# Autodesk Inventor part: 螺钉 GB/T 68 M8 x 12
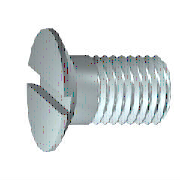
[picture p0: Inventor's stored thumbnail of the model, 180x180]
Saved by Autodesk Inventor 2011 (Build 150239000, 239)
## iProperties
Created: 2010-02
Part Number: 螺钉 GB/T 68 M8 x 12
Material: 低炭钢
Description: 开槽沉头螺钉
Document SubType Name: Modeling
Standard: GB/T 68-2000
Designer: user
Standard Revision: 2000
Standards Organization: GB
Language: zh-CN
Size Designation: M8x12
Categories: <MemberInstance><Categories><Category DisplayName="紧固件" InternalName="e4da775c-781d-43d5-af7c-5136215cf5a6" Mnemonic="FSTN"><Category DisplayName="螺栓" InternalN
Density: 1 g/cm^3
IsCustomPart: 1
Author: user
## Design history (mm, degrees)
body "Solid1"
sketch "Sketch1"
  geometry: L1 (5.056, 3.594)-(0.75, 7.9); L2 (0.75, 7.9)-(0, 7.9); L3 (0, 7.9)-(0, 0); L4 (0, 0)-(12, 0); L5 (12, 4)-(7.15, 4); L6 (7.15, 4)-(6.383, 3.594); L7 (6.383, 3.594)-(5.056, 3.594); L8 (7.15, 4)-(4.65, 4); L9 (12, 0)-(12, 4); L10 (-2.4, 0)-(14.4, 0) reference; L11 (0, 9.48)-(0, -1.58) reference
  constraints: 18 end point, 4 parallel, 2 collinear, 2 perpendicular, 1 horizontal, 1 point on line
  dimensions: "d0" = 12 distance of L3.end L4.end (= NLG); "d1" = 45 deg angle of L1 L4 (= 0.5 x SEWI); "d2" = 0.76681 horizontal distance of L5.end L6.end (= GAL); "d3" = 4.85 distance from line of L9 L5.end (= GEL); "d4" = 4.65 distance from line of L8.end L3 (= KOH); "d5" = 7.188 diameter of L6.end L4 (= BDM); "d6" = 8 diameter of L5 L4 (= GD); "d7" = 15.8 diameter of L2 L4 (= KOD)
workplane "Work Plane1"
fillet "Fillet" dims "d41" = 2 (= RR)
revolve "Body" stored, may be unused: angle "d19" = 90 deg
sketch "Sketch2"
  geometry: L1 (7.9, -1)-(-7.9, -1); L2 (-7.9, -1)-(-7.9, 1); L3 (-7.9, 1)-(7.9, 1); L4 (7.9, 1)-(7.9, -1); L5 (0, 1)-(0, -1); L6 (-7.9, 0)-(7.9, 0); L7 (0, 7.9)-(0, 0) reference; 2 further points
  constraints: 12 end point, 5 midpoint, 2 parallel, 1 collinear, 1 horizontal, 1 perpendicular
  dimensions: "d15" = 2 distance of L3.end L1.start (= SBR); "d16" = 15.8 distance of L1.start L1.end (= KOD)
extrude "Slot" cut sketch "Sketch2" distance "d8" = 2.3 (= STI); taper "d9" = 0 deg
feature "Thread" dims "d10" = 4.85 (= GEL), "d11" = 0
chamfer "Chamfer1" distance "d12" = 0.76681 (= -0.5 x SPD + 0.5 x GD); stored, may be unused: second distance "d13" = 0.38341 (= 0.5 x GAL), angle "d35" = 45 deg
other parameters: "NLG" = 12 [user parameter; used in 1 equation term], "GAL" = 0.76681 (= 0.61345 x PTC) [user parameter; used in 2 equation terms], "GEL" = 4.85 [user parameter; used in 2 equation terms], "KOH" = 4.65 [user parameter; used in 1 equation term], "KOD" = 15.8 [user parameter; used in 2 equation terms], "SEWI" = 90 deg [user parameter; used in 1 equation term], "BDM" = 7.188 [user parameter; used in 1 equation term], "GD" = 8 (= NND) [user parameter; used in 2 equation terms], "SBR" = 2 [user parameter; used in 1 equation term], "STI" = 2.3 [user parameter; used in 1 equation term], "d17" = 0, "SPD" = 6.46637 (= NND - 1.2269 x PTC) [user parameter; used in 1 equation term], "d39" = 0, "d40" = 0, "RR" = 2 [user parameter; used in 1 equation term], "GUL" = 0.76681 (= 0.61345 x PTC) [user parameter], "PTC" = 1.25 [user parameter; used in 5 equation terms], "EPV" = 8.65 [user parameter], "THREADDIA" = 8 [user parameter; used in 1 equation term], "TOA" = 30 deg [user parameter], "FAWI" = 90 deg [user parameter], "TPU" = 8 (computed from PTC) [user parameter], "NND" = 8 [user parameter; used in 2 equation terms], "GD1" = 6.46637 (= THREADDIA - 1.2269 x PTC) [user parameter]
